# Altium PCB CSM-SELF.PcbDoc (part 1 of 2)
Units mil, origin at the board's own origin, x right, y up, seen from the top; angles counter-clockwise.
Board outline 6400 x 4000 mil, 2 copper layers (Top Layer, Bottom Layer), stack 62 mil thick; 115 components, 107 nets, 450 pads, 129 vias.
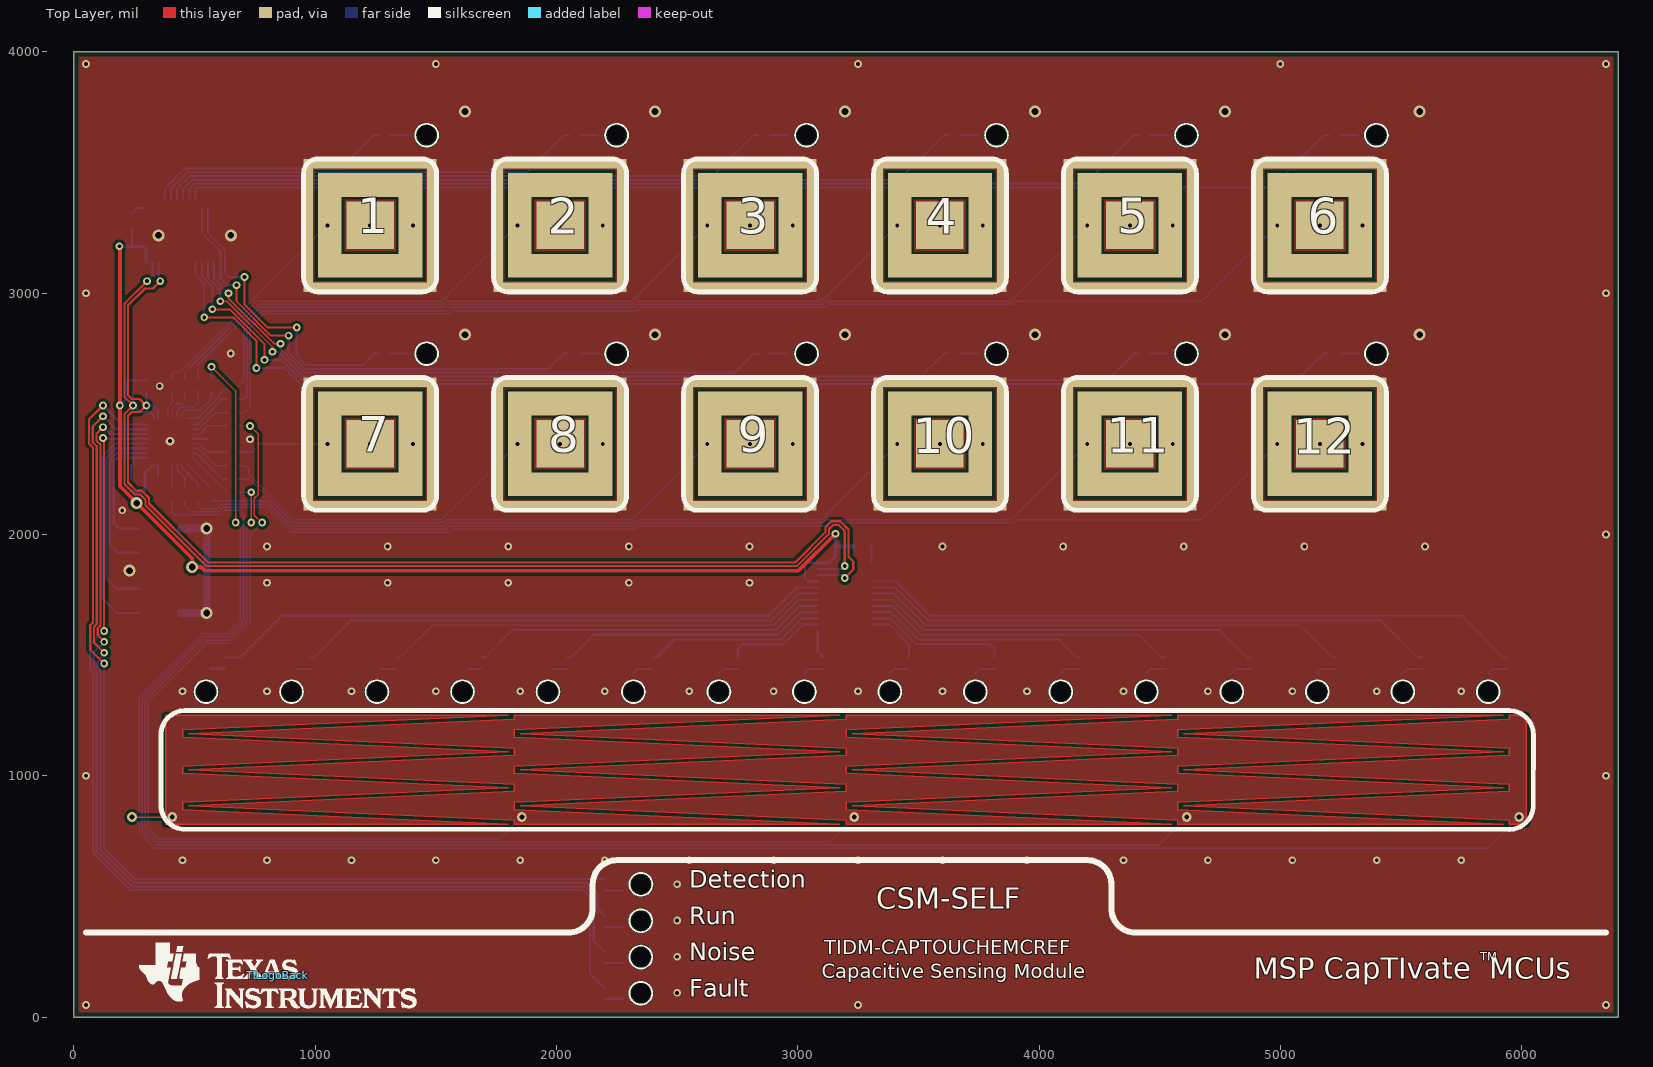
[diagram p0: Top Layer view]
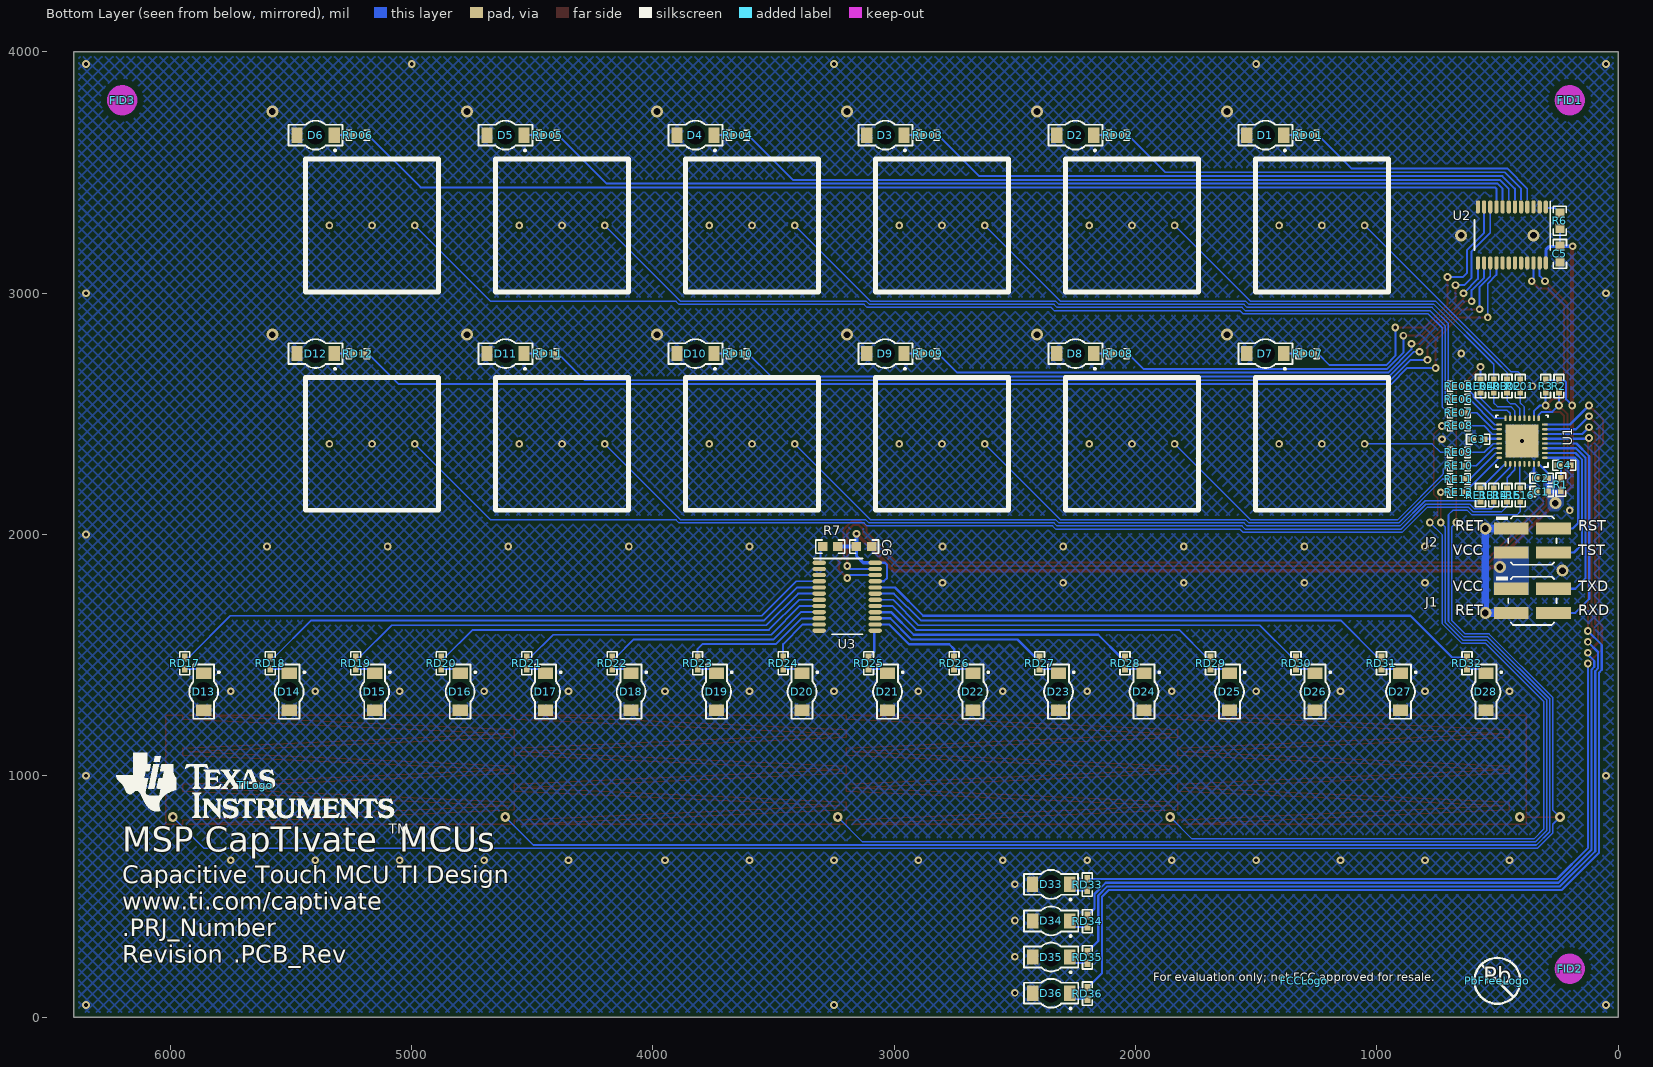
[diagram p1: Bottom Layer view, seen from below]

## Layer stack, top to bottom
Top Solder: solder mask 0.4, Solder Resist, Dk 3.5
Top Layer: signal copper 1.4
Dielectric1: core 59.2, FR-4, Dk 4.8
Bottom Layer: signal copper 1.4
Bottom Solder: solder mask 0.4, Solder Resist, Dk 3.5

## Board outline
0,0 6400,0 6400,4000 0,4000

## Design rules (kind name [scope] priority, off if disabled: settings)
AcuteAngle [All] p1: minimum=4.50000000000000E+0001 checktracksonly=FALSE
AssemblyTestPointUsage [All] p1: valid=2
Clearance Clearance_Keepouts [((IsTrack Or IsArc) And Not InPoly) And IsFree and IsKeepOut vs ((IsTrack Or IsArc) And Not InPoly) And IsFree and IsKeepOut] p1: gap=0
Clearance Clearance_BoardEdge_MountingHoles [OnCopper and InComponentClass('Mounting Holes') vs IsKeepOut] p2: gap=40
Clearance Clearance_BoardEdge_Poly [OnCopper and InPoly vs IsKeepOut] p3: gap=25
Clearance Clearance_BoardEdge [OnCopper and Not InComponentClass('Logo') and not InComponentClass('FiducialMark') and not InRegion(1000,500,4000,800) and Not IsKeepout vs IsKeepOut] p4: gap=75
Clearance Clearance_Poly [InPolygon] p5: gap=12
Clearance [All] p6: gap=6.3
ComponentClearance ComponentClearance_MountingHoles_FiducialMarks [InComponentClass('Mounting Holes') vs InComponentClass('FiducialMark')] p1: gap=50 collisioncheckmode=3 verticalgap=10 showdistances=FALSE
ComponentClearance ComponentClearance_Shunt [InComponentClass('Header') vs InComponentClass('Shunt')] p2: gap=0 collisioncheckmode=3 verticalgap=0 showdistances=FALSE
ComponentClearance ComponentClearance_Logo [InComponentClass('Logo')] p3: gap=50 collisioncheckmode=3 verticalgap=10 showdistances=FALSE
ComponentClearance ComponentClearance_ScrewToNut [(HasFootprint('NY PMS 440 0025 PH')) vs (HasFootprint('Keystone_1902C'))] p4: gap=5 collisioncheckmode=3 verticalgap=10 showdistances=FALSE
ComponentClearance ComponentClearance_MountingHoles [InComponentClass('Mounting Holes')] p5: gap=250 collisioncheckmode=3 verticalgap=100000 showdistances=FALSE
ComponentClearance ComponentClearance_SmallPassives [HasFootprint('0201*') or HasFootprint('0402*') or HasFootprint('0508') or HasFootprint('0603*') or HasFootprint('0612') or HasFootprint('0805*') or HasFootprint('0815*') or HasFootprint('0830*') or HasFootprint('1206*') or HasFootprint('1210*') or HasFootprint('1808*') or HasFootprint('1812*') or HasFootprint('1825*') or HasFootprint('2010*') or HasFootprint('2220*') or HasFootprint('2225*') or HasFootprint('2512*') or HasFootprint('2728*') or HasFootprint('3518*') vs HasFootprint('0201*') or HasFootprint('0402*') or HasFootprint('0508') or HasFootprint('0603*') or HasFootprint('0612') or HasFootprint('0805*') or HasFootprint('0815*') or HasFootprint('0830*') or HasFootprint('1206*') or HasFootprint('1210*') or HasFootprint('1808*') or HasFootprint('1812*') or HasFootprint('1825*') or HasFootprint('2010*') or HasFootprint('2220*') or HasFootprint('2225*') or HasFootprint('2512*') or HasFootprint('2728*') or HasFootprint('3518*')] p6: gap=7.87 collisioncheckmode=3 verticalgap=10 showdistances=FALSE
ComponentClearance ComponentClearance_THtoSMT [IsThruComponent vs IsSMTComponent] p7: gap=7.87 collisioncheckmode=3 verticalgap=30 showdistances=FALSE
ComponentClearance ComponentClearance_THtoTH [IsThruComponent vs IsThruComponent] p8: gap=7.87 collisioncheckmode=3 verticalgap=30 showdistances=FALSE
ComponentClearance [All] p9: gap=7.87 collisioncheckmode=3 verticalgap=10 showdistances=FALSE
DiffPairsRouting [All] p1: maxlimit=100 minlimit=10 mostfreqgap=10 toplayer_minwidth=15 toplayer_maxwidth=15 toplayer_prefwidth=15 bottomlayer_minwidth=15 bottomlayer_maxwidth=15 bottomlayer_prefwidth=15 maxuncoupledlength=1000
FabricationTestPointUsage TestPointUsage [All] p1: valid=2 allowmultiple=FALSE
FabricationTestpoint Testpoint [All] p1: side=3 testpointundercomponent=TRUE minsize=40 maxsize=100 preferedsize=60 minholesize=0 maxholesize=40 preferedholesize=32 testpointgrid=1 allowsidetop=TRUE allowsidebottom=TRUE usegrid=TRUE gridtolerance=0.01
FanoutControl Fanout_LCC [IsLCC] p1: bgadir=Out bgaviamode=Centered fanoutstyle=Auto fanoutdirection=Alternating viagrid=1 // Fanout_LCC (Default Rule)
FanoutControl Fanout_BGA [IsBGA] p2: bgadir=Out bgaviamode=Centered fanoutstyle=Auto fanoutdirection=Alternating viagrid=1 // Fanout_BGA (Default Rule)
FanoutControl Fanout_Default [All] p4: bgadir=Out bgaviamode=Centered fanoutstyle=Auto fanoutdirection=Alternating viagrid=1 // Fanout_Default (Default Rule)
FanoutControl Fanout_Small [(CompPinCount < 5)] p5: bgadir=Out bgaviamode=Centered fanoutstyle=Auto fanoutdirection=OutThenIn viagrid=1 // Fanout_Small (Default Rule)
HoleSize [All] p1: absolutevalues=TRUE maxlimit=251 minlimit=8 maxpercent=80.000 minpercent=20.000
MinimumAnnularRing MinimumAnnularRing_ThermalPadVias [IsVia and InAnyComponent] p1: minimumring=5.91
MinimumAnnularRing [All] p2: minimumring=3.94
MinimumSolderMaskSliver MinimumSolderMaskSliver_Logo [InComponentClass('Logo') vs InComponentClass('Logo')] p1: minsoldermaskwidth=0.7
MinimumSolderMaskSliver [All] p2: minsoldermaskwidth=3.94
PlaneClearance [All] p1: clearance=19.68
PlaneConnect [All] p1: planeconnectstyle=Relief reliefexpansion=10 reliefentries=4 reliefconductorwidth=10 reliefairgap=10
PolygonConnect [All] p1: connectstyle=Direct reliefconductorwidth=10 reliefentries=4 polygonreliefangle="90 Angle" airgapwidth=10
RoutingVias ThermalPadVias [IsVia and InAnyComponent] p1: holewidth=7.87 width=19.68 viastyle="Through Hole" minholewidth=7.87 minwidth=19.68 maxholewidth=12.99 maxwidth=23.62
RoutingVias [All] p2: holewidth=16 width=34 viastyle="Through Hole" minholewidth=7.87 minwidth=26 maxholewidth=40 maxwidth=65
SilkToBoardRegionClearance [Not ((IsComment or IsDesignator) And (Hide <> 'False')) and not InRegion(1000,500,4000,800)] p1:
SilkToSilkClearance SilkToSilkClearance_Pb-FreeLogo [(HasFootprint('Pb-Free_Overlay_Medium') OR HasFootprint('Pb-Free_Overlay_Small')) vs (HasFootprint('Pb-Free_Overlay_Medium') OR HasFootprint('Pb-Free_Overlay_Small'))] p1: silktosilkclearance=0
SilkToSilkClearance [All] p2: silktosilkclearance=5
SilkToSolderMaskClearance "Silk to Solder Mask Opening" [All] p1: minsilkscreentomaskgap=1 clearancetoexposedcopper=FALSE
SolderMaskExpansion [All] p1: expansion=1.9
Width [All] p1: maxlimit=100 minlimit=6 preferedwidth=10 checkconnectedcopper=TRUE
14 further rules are at their usual default settings.

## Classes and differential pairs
component class FiducialMark: FID1 FID2 FID3
component class Logo: TILogo TILogoBack
component class CSM-SELF__TopLevel: FCCLogo FID1 FID2 FID3 PbFreeLogo TILogo TILogoBack
component class CSM-SELF__LEDDrive: C5 C6 D1 D2 D3 D4 D5 D6 D7 D8 D9 D10 D11 D12 D13 D14 D15 D16 D17 D18 D19 D20 D21 D22 D23 D24 D25 D26 D27 D28 D33 D34 D35 D36 R6 R7 RD01 RD02 RD03 RD04 RD05 RD06 RD07 RD08 RD09 RD10 RD11 RD12 RD17 RD18 RD19 RD20 RD21 RD22 RD23 RD24 RD25 RD26 RD27 RD28 RD29 RD30 RD31 RD32 RD33 RD34 RD35 RD36 U2 U3
component class Header: J1 J2
component class CSM-SELF__MCU: C1 C2 C3 C4 J1 J2 R1 R2 R3 U1
net class LED[1..28]: LED1 LED2 LED3 LED4 LED5 LED6 LED7 LED8 LED9 LED10 LED11 LED12 LED13 LED14 LED15 LED16 LED17 LED18 LED19 LED20 LED21 LED22 LED23 LED24 LED25 LED26 LED27 LED28
component class CSM-SELF__CapacitiveTouch: 1 2 3 4 5 6 7 8 9 10 11 12 RE01 RE02 RE03 RE04 RE05 RE06 RE07 RE08 RE09 RE10 RE11 RE12 RE13 RE14 RE15 RE16

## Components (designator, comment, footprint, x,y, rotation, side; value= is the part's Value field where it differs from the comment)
1 "Btn-Self-EMC" btn-self-emc 951.81,3005.51 r0 top
2 "Btn-Self-EMC" btn-self-emc 1739.21,3005.51 r0 top
3 "Btn-Self-EMC" btn-self-emc 2526.61,3005.51 r0 top
4 "Btn-Self-EMC" btn-self-emc 3314.02,3005.51 r0 top
5 "Btn-Self-EMC" btn-self-emc 4101.42,3005.51 r0 top
6 "Btn-Self-EMC" btn-self-emc 4888.82,3005.51 r0 top
7 "Btn-Self-EMC" btn-self-emc 951.81,2100 r0 top
8 "Btn-Self-EMC" btn-self-emc 1739.21,2100 r0 top
9 "Btn-Self-EMC" btn-self-emc 2526.61,2100 r0 top
10 "Btn-Self-EMC" btn-self-emc 3314.02,2100 r0 top
11 "Btn-Self-EMC" btn-self-emc 4101.42,2100 r0 top
12 "Btn-Self-EMC" btn-self-emc 4888.82,2100 r0 top
C1 "C1005X5R0J475M050BC" 0402 316.83,2178.05 r0 bottom
C2 "C1005X5R0J104K" 0402 316.83,2233.05 r0 bottom
C3 "C1005X5R0J105M" 0402 580,2395 r0 bottom
C4 "GRM1555C1E511JA01D" 0402 222.9,2286.98 r180 bottom
C5 "0603YC104JAT2A" 0603 241.18,3162.99 r270 bottom
C6 "0603YC104JAT2A" 0603 3125,1949.61 r180 bottom
D1 "Orange LED" 1206_ReverseMount_LED 1361.26,3623.62 r0 top
D2 "Orange LED" 1206_ReverseMount_LED 2148.66,3623.62 r0 top
D3 "Orange LED" 1206_ReverseMount_LED 2936.06,3623.62 r0 top
D4 "Orange LED" 1206_ReverseMount_LED 3723.46,3623.62 r0 top
D5 "Orange LED" 1206_ReverseMount_LED 4510.87,3623.62 r0 top
D6 "Orange LED" 1206_ReverseMount_LED 5298.27,3623.62 r0 top
D7 "Orange LED" 1206_ReverseMount_LED 1361.26,2718.11 r0 top
D8 "Orange LED" 1206_ReverseMount_LED 2148.66,2718.11 r0 top
D9 "Orange LED" 1206_ReverseMount_LED 2936.06,2718.11 r0 top
D10 "Orange LED" 1206_ReverseMount_LED 3723.46,2718.11 r0 top
D11 "Orange LED" 1206_ReverseMount_LED 4510.87,2718.11 r0 top
D12 "Orange LED" 1206_ReverseMount_LED 5298.27,2718.11 r0 top
D13 "Orange LED" 1206_ReverseMount_LED 5830.79,1448.82 r270 top
D14 "Orange LED" 1206_ReverseMount_LED 5476.46,1448.82 r270 top
D15 "Orange LED" 1206_ReverseMount_LED 5122.13,1448.82 r270 top
D16 "Orange LED" 1206_ReverseMount_LED 4767.8,1448.82 r270 top
D17 "Orange LED" 1206_ReverseMount_LED 4413.46,1448.82 r270 top
D18 "Orange LED" 1206_ReverseMount_LED 4059.13,1448.82 r270 top
D19 "Orange LED" 1206_ReverseMount_LED 3704.8,1448.82 r270 top
D20 "Orange LED" 1206_ReverseMount_LED 3350.47,1448.82 r270 top
D21 "Orange LED" 1206_ReverseMount_LED 2996.14,1448.82 r270 top
D22 "Orange LED" 1206_ReverseMount_LED 2641.81,1448.82 r270 top
D23 "Orange LED" 1206_ReverseMount_LED 2287.48,1448.82 r270 top
D24 "Orange LED" 1206_ReverseMount_LED 1933.15,1448.82 r270 top
D25 "Orange LED" 1206_ReverseMount_LED 1578.82,1448.82 r270 top
D26 "Orange LED" 1206_ReverseMount_LED 1224.49,1448.82 r270 top
D27 "Orange LED" 1206_ReverseMount_LED 870.16,1448.82 r270 top
D28 "Orange LED" 1206_ReverseMount_LED 515.83,1448.82 r270 top
D33 "Yellow-Green LED" 1206_ReverseMount_LED 2249.61,518.5 r0 top
D34 "Yellow-Green LED" 1206_ReverseMount_LED 2249.21,367.01 r0 top
D35 "Yellow LED" 1206_ReverseMount_LED 2249.21,217.01 r0 top
D36 "Red LED" 1206_ReverseMount_LED 2249.21,67.01 r0 top
FCCLogo "FCC disclaimer" FCC_disclaimer 1300,150 r180 bottom
FID1 "Fiducial" Fiducial10-30 200,3800 r180 bottom
FID2 "Fiducial" Fiducial10-30 200,200 r180 bottom
FID3 "Fiducial" Fiducial10-30 6200,3800 r180 bottom
J1 "15-91-2040" Molex_15-91-2040 355,1725.01 r270 bottom
J2 "15-91-2040" Molex_15-91-2040 355,1975 r270 bottom
PbFreeLogo "Pb-Free Symbol" Pb-Free_Overlay_Medium 500,150 r180 bottom
R1 "CRCW040247K0JNED" 0402 236.83,2206.67 r270 bottom
R2 "CRCW04022K20JNED" 0402 245,2615 r270 bottom
R3 "CRCW04022K20JNED" 0402 300,2615 r270 bottom
R6 "CRCW060310K0JNEA" 0603 241.18,3300.79 r90 bottom
R7 "CRCW060310K0JNEA" 0603 3265,1949.61 r0 bottom
RD01 "CRCW0402620RJNED" 0402 1286.46,3655.12 r0 bottom
RD02 "CRCW0402620RJNED" 0402 2073.86,3655.12 r0 bottom
RD03 "CRCW0402620RJNED" 0402 2861.26,3655.12 r0 bottom
RD04 "CRCW0402620RJNED" 0402 3648.66,3655.12 r0 bottom
RD05 "CRCW0402620RJNED" 0402 4436.06,3655.12 r0 bottom
RD06 "CRCW0402620RJNED" 0402 5223.46,3655.12 r0 bottom
RD07 "CRCW0402620RJNED" 0402 1286.46,2749.61 r0 bottom
RD08 "CRCW0402620RJNED" 0402 2073.86,2749.61 r0 bottom
RD09 "CRCW0402620RJNED" 0402 2861.26,2749.61 r0 bottom
RD10 "CRCW0402620RJNED" 0402 3648.66,2749.61 r0 bottom
RD11 "CRCW0402620RJNED" 0402 4436.06,2749.61 r0 bottom
RD12 "CRCW0402620RJNED" 0402 5223.46,2749.61 r0 bottom
RD17 "CRCW0402620RJNED" 0402 5941.02,1466.54 r270 bottom
RD18 "CRCW0402620RJNED" 0402 5586.69,1466.54 r270 bottom
RD19 "CRCW0402620RJNED" 0402 5232.36,1466.54 r270 bottom
RD20 "CRCW0402620RJNED" 0402 4878.03,1466.54 r270 bottom
RD21 "CRCW0402620RJNED" 0402 4523.7,1466.54 r270 bottom
RD22 "CRCW0402620RJNED" 0402 4169.37,1466.54 r270 bottom
RD23 "CRCW0402620RJNED" 0402 3815.04,1466.54 r270 bottom
RD24 "CRCW0402620RJNED" 0402 3460.71,1466.54 r270 bottom
RD25 "CRCW0402620RJNED" 0402 3106.38,1466.54 r270 bottom
RD26 "CRCW0402620RJNED" 0402 2752.05,1466.54 r270 bottom
RD27 "CRCW0402620RJNED" 0402 2397.72,1466.54 r270 bottom
RD28 "CRCW0402620RJNED" 0402 2043.39,1466.54 r270 bottom
RD29 "CRCW0402620RJNED" 0402 1689.06,1466.54 r270 bottom
RD30 "CRCW0402620RJNED" 0402 1334.72,1466.54 r270 bottom
RD31 "CRCW0402620RJNED" 0402 980.39,1466.54 r270 bottom
RD32 "CRCW0402620RJNED" 0402 626.06,1466.54 r270 bottom
RD33 "CRCW0402620RJNED" 0402 2199.61,548.5 r270 bottom
RD34 "CRCW0402620RJNED" 0402 2199.21,397.01 r270 bottom
RD35 "CRCW0402620RJNED" 0402 2199.21,247.01 r270 bottom
RD36 "CRCW0402620RJNED" 0402 2199.21,97.01 r270 bottom
RE01 "CRCW0402470RJNED" 0402 405,2615 r90 bottom
RE02 "CRCW0402470RJNED" 0402 460,2615 r90 bottom
RE03 "CRCW0402470RJNED" 0402 515,2615 r90 bottom
RE04 "CRCW0402470RJNED" 0402 570,2615 r90 bottom
RE05 "CRCW0402470RJNED" 0402 660,2615 r0 bottom
RE06 "CRCW0402470RJNED" 0402 660,2560 r0 bottom
RE07 "CRCW0402470RJNED" 0402 660,2505 r0 bottom
RE08 "CRCW0402470RJNED" 0402 660,2450 r0 bottom
RE09 "CRCW0402470RJNED" 0402 660,2340 r0 bottom
RE10 "CRCW0402470RJNED" 0402 660,2285 r0 bottom
RE11 "CRCW0402470RJNED" 0402 660,2230 r0 bottom
RE12 "CRCW0402470RJNED" 0402 660,2175 r0 bottom
RE13 "CRCW0402470RJNED" 0402 570,2163.62 r270 bottom
RE14 "CRCW0402470RJNED" 0402 515,2163.62 r270 bottom
RE15 "CRCW0402470RJNED" 0402 460,2163.62 r270 bottom
RE16 "CRCW0402470RJNED" 0402 405,2163.62 r270 bottom
TILogo "Texas Instruments" TI_Stacked_Overlay_Medium 5648.66,960 r180 bottom
TILogoBack "Texas Instruments" TI_Stacked_Overlay_Medium 845,172.71 r0 top
U1 "MSP430FR2633IRHB" RHB0032E_NV 397.9,2386.98 r0 bottom
U2 "TCA9535PWR" PW0024A_N 440,3241.73 r270 bottom
U3 "TCA9535PWR" PW0024A_N 3194.96,1742.13 r180 bottom

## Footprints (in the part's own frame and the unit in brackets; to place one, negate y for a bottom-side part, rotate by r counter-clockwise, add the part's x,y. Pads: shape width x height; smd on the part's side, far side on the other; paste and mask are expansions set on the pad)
0402 [mm] "0402 from SM-752 data"
  rect 0.8x0.6 smd: 1(-0.6,0) 2(0.6,0)
  silkscreen extent -1.22,-0.52 1.22,0.52, body extent -0.55,-0.3 0.55,0.3, height 0.6
0603 [mm] "0603 from SM-752 data"
  rect 1x0.95 smd: 1(-0.8,0) 2(0.8,0)
  silkscreen extent -1.52,-0.69 1.52,0.69, body extent -0.87,-0.47 0.87,0.47, height 1
1206_ReverseMount_LED [mm]
  rect 1.2x1.6 smd far side: 1(0.6,0.8) 2(4.5,0.8)
  round 0 hole 2 unplated: ""(2.55,0.8)
  silkscreen extent 1.35,-0.4 3.75,2
btn-self-emc [mm] "Mutual Capacitance Button with EMC"
  rect 1x14 smd paste+0: GND(0.5,7)
  rect 14x1 smd paste+0 mask+0: GND(7,0.5) GND(7,13.5)
  round 0.81 hole 0.406: GND(7,7) RX(2.5,7) RX(11.5,7)
  rect 5x5 smd paste+0 mask+0: GND(7,7)
  rect 1x14 smd paste+0 mask+0: GND(13.5,7)
  rect 2.5x11 smd paste+0: RX(2.75,7) RX(11.25,7)
  rect 11x2.5 smd paste+0: RX(7,2.75) RX(7,11.25)
  silkscreen extent 0,0 14,14
FCC_disclaimer [mil]
Fiducial10-30 [mm]
  round 1 smd mask+1: 1(0,0)
  Top Layer keep-out circle w1.678: c0,0 r0.75
Molex_15-91-2040 [mil] "Molex"
  rect 50x144.88 smd: 1(-50,-87.5) 2(-50,87.5) 3(50,-87.5) 4(50,87.5)
  silkscreen extent -100,-150 100,100, body extent -100,-137 100,138, height 380
Pb-Free_Overlay_Medium [mil]
  silkscreen extent -95,-95 95,95
PW0024A_N [mm] "TSOP, 24-Leads, Body 7.8x4.4mm, Pitch 0.65mm, IPC Medium Density"
  oval 1.4x0.45 smd: 1(-2.95,3.575) 2(-2.95,2.925) 3(-2.95,2.275) 4(-2.95,1.625) 5(-2.95,0.975) 6(-2.95,0.325) 7(-2.95,-0.325) 8(-2.95,-0.975) 9(-2.95,-1.625) 10(-2.95,-2.275) 11(-2.95,-2.925) 12(-2.95,-3.575) 13(2.95,-3.575) 14(2.95,-2.925) 15(2.95,-2.275) 16(2.95,-1.625) 17(2.95,-0.975) 18(2.95,-0.325) 19(2.95,0.325) 20(2.95,0.975) 21(2.95,1.625) 22(2.95,2.275) 23(2.95,2.925) 24(2.95,3.575)
  silkscreen extent -3.51,-3.95 1.6,4.04, body extent -3.21,-3.9 3.21,3.9, height 1
RHB0032E_NV [mm] "QFN, 32-Leads, Body 5x5mm, Pitch 0.5mm, Thermal Pad 3.45x3.45mm, TI Recommended"
  oval 0.6x0.24 smd: 1(-2.4,1.75) 2(-2.4,1.25) 3(-2.4,0.75) 4(-2.4,0.25) 5(-2.4,-0.25) 6(-2.4,-0.75) 7(-2.4,-1.25) 8(-2.4,-1.75) 17(2.4,-1.75) 18(2.4,-1.25) 19(2.4,-0.75) 20(2.4,-0.25) 21(2.4,0.25) 22(2.4,0.75) 23(2.4,1.25) 24(2.4,1.75)
  oval 0.24x0.6 smd: 9(-1.75,-2.4) 10(-1.25,-2.4) 11(-0.75,-2.4) 12(-0.25,-2.4) 13(0.25,-2.4) 14(0.75,-2.4) 15(1.25,-2.4) 16(1.75,-2.4) 25(1.75,2.4) 26(1.25,2.4) 27(0.75,2.4) 28(0.25,2.4) 29(-0.25,2.4) 30(-0.75,2.4) 31(-1.25,2.4) 32(-1.75,2.4)
  rect 3.45x3.45 smd paste-1.725: 33(0,0)
  silkscreen extent -2.72,-2.73 2.72,2.73, body extent -2.57,-2.57 2.58,2.58, height 1.01
TI_Stacked_Overlay_Medium [mil]
  silkscreen extent -576,-136 576,135

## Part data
1 2 3 4 5 6 7 8 9 10 11 12: library part btn-self-emc, "Capacitive Button, Self Capacitance, 2-Layer, High EMC"
C1: "CAP, CERM, 4.7 µF, 6.3 V, +/- 20%, X5R, 0402"
C2: "CAP, CERM, 0.1 µF, 6.3 V, +/- 10%, X5R, 0402"
C3: "CAP, CERM, 1 µF, 6.3 V, +/- 20%, X5R, 0402"
C4: "CAP, CERM, 510 pF, 25 V, +/- 5%, C0G/NP0, 0402"
C5 C6: "CAP, CERM, 0.1 µF, 16 V, +/- 5%, X7R, 0603"
D1 D2 D3 D4 D5 D6 D7 D8 D9 D10 D11 D12 D13 D14 D15 D16 D17 D18 D19 D20 D21 D22 D23 D24 D25 D26 D27 D28: library part 597-6201-607F, "LED, Orange, SMD, Reverse Mount, 1206"
D33 D34: library part 597-6501-607F, "LED, Yellow-Green, SMD, Reverse Mount, 1206"
D35: library part 597-6401-607F, "LED, Yellow, SMD, Reverse Mount, 1206"
D36: library part 597-6001-607F, "LED, Red, SMD, Reverse Mount, 1206"
FCCLogo: library part FCC_disclaimer, "FCC_disclaimer"
FID1 FID2 FID3: "Fiducial mark.  There is nothing to buy or mount."
J1 J2: "Header, 100mil, 2x2, Tin, SMT"
PbFreeLogo: library part Pb-Free
R1: "RES, 47 k, 5%, 0.063 W, 0402"
R2 R3: "RES, 2.2 k, 5%, 0.063 W, 0402"
R6 R7: "RES, 10 k, 5%, 0.1 W, 0603"
RD01 RD02 RD03 RD04 RD05 RD06 RD07 RD08 RD09 RD10 RD11 RD12 RD17 RD18 RD19 RD20 RD21 RD22 RD23 RD24 RD25 RD26 RD27 RD28 RD29 RD30 RD31 RD32 RD33 RD34 RD35 RD36: "RES, 620, 5%, 0.063 W, 0402"
RE01 RE02 RE03 RE04 RE05 RE06 RE07 RE08 RE09 RE10 RE11 RE12 RE13 RE14 RE15 RE16: "RES, 470, 5%, 0.063 W, 0402"
TILogo TILogoBack: library part TI_Logo, "Texas Instrument Corporate Signature"
U1: "MSP430 Captivate Microcontroller"
U2 U3: "Remote 16-Bit I2C and SMBus, Low-Power I/O Expander with Interrupt Output and Config Register, 1.65 to 5.5 V, -40 to 85 degC, 24-pin TSSOP (PW), Green (RoHS & no Sb/Br)"

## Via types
v1: diameter 32, hole 16, Top Layer to Bottom Layer, tented both sides, 103 vias
v2: diameter 50, hole 28, Top Layer to Bottom Layer, tented both sides, 19 vias
v3: diameter 40, hole 20, Top Layer to Bottom Layer, tented both sides, 6 vias
v4: diameter 36, hole 16, Top Layer to Bottom Layer, 1 vias

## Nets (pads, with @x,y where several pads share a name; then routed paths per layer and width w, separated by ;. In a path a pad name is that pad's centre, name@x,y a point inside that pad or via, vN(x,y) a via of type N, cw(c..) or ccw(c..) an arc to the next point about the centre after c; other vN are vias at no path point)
CAP0.0: RE01.1 U1.12 | length 116.9
  Bottom Layer w6.3: U1.12@388.05,2481.47 388.05,2528.05 405,2545 RE01.1@405,2591.38
CAP0.1: RE02.1 U1.13 | length 143.3
  Bottom Layer w6.3: U1.13@407.74,2481.47 407.74,2522.74 427.6,2542.6 447.6,2542.6 460,2555 RE02.1@460,2591.38
CAP0.2: RE03.1 U1.14 | length 184.5
  Bottom Layer w6.3: U1.14@427.42,2481.47 427.42,2512.42 445,2530 500,2530 515,2545 RE03.1@515,2591.38 ; RE03.1@510.69,2595.69 RE03.1@515,2600
CAP0.3: RE04.1 U1.15 | length 196
  Bottom Layer w6.3: U1.15@447.11,2481.47 447.11,2502.11 460,2515 520,2515 570,2565 RE04.1@570,2591.38
CAP1.0: RE05.1 U1.16 | length 215.2
  Bottom Layer w6: U1.16@466.8,2481.47 511.47,2481.47 600,2570 600,2580 RE05.1@625,2605
CAP1.1: RE06.1 U1.17 | length 187.1
  Bottom Layer w6: U1.17@492.39,2455.88 510.88,2455.88 615,2560 RE06.1@636.38,2560
CAP1.2: RE07.1 U1.18 | length 172.5
  Bottom Layer w6: U1.18@492.39,2436.2 516.2,2436.2 585,2505 RE07.1@636.38,2505
CAP1.3: RE08.1 U1.19 | length 157.9
  Bottom Layer w6: U1.19@492.39,2416.51 521.51,2416.51 555,2450 RE08.1@636.38,2450
CAP2.0: RE09.1 U1.21 | length 159.4
  Bottom Layer w6: U1.21@492.39,2377.14 517.86,2377.14 555,2340 RE09.1@636.38,2340
CAP2.1: RE10.1 U1.22 | length 174
  Bottom Layer w6: U1.22@492.39,2357.46 514.74,2357.46 587.2,2285 RE10.1@636.38,2285
CAP2.2: RE11.1 U1.23 | length 188.6
  Bottom Layer w6: U1.23@492.39,2337.77 507.23,2337.77 615,2230 RE11.1@636.38,2230
CAP2.3: RE12.1 U1.24 | length 194.6
  Bottom Layer w6: U1.24@492.39,2318.09 RE12.1@630,2180.47
CAP3.0: RE13.1 U1.25 | length 146
  Bottom Layer w6: U1.25@466.8,2292.5 RE13.1@570,2189.29
CAP3.1: RE14.1 U1.26 | length 133.4
  Bottom Layer w6: U1.26@447.11,2292.5 447.11,2277.89 515,2210 RE14.1@515,2187.24
CAP3.2: RE15.1 U1.27 | length 118.7
  Bottom Layer w6: U1.27@427.42,2292.5 427.42,2267.58 460,2235 RE15.1@460,2187.24
CAP3.3: RE16.1 U1.28 | length 102.5
  Bottom Layer w6.3: RE16.1@407.74,2189.98 U1.28@407.74,2292.5
CAPTIVATE_VREG: C3.1 U1.20 | length 62.2
  Bottom Layer w9: U1.20@492.39,2396.83 C3.1@554.55,2396.83
DETECT: RD33.1 U1.8 | length 4237.9
  Top Layer w9: v1(120,2535) 62.6,2477.6 62.6,2376.23 79.1,2359.73 79.1,1635.27 67.6,1623.77 67.6,1522.4 v1(125,1465)
  Bottom Layer w9: v1(120,2535) 199.12,2455.88 U1.8@303.41,2455.88 ; v1(125,1465) 125,700 252.87,572.13 RD33.1@2199.61,572.13
FAULT: RD36.1 U1.5 | length 4457
  Top Layer w9: v1(125,1600) v1@125,2395
  Bottom Layer w9: v1(125,1600) 67.6,1542.6 67.6,1438.83 79.1,1427.33 79.1,680.99 233.86,526.23 2110.5,526.23 2139.4,497.33 2139.4,180.44 RD36.1@2199.21,120.63 ; v1@126.83,2396.83 U1.5@303.41,2396.83
  other v1: 120,2400
LED1: D1.1 RD01.2 | length 74.8
  Bottom Layer w7.87: RD01.2@1310.08,3655.12 D1.1@1384.88,3655.12
LED2: D2.1 RD02.2 | length 74.8
  Bottom Layer w7.87: RD02.2@2097.48,3655.12 D2.1@2172.28,3655.12
LED3: D3.1 RD03.2 | length 74.8
  Bottom Layer w7.87: RD03.2@2884.88,3655.12 D3.1@2959.68,3655.12
LED4: D4.1 RD04.2 | length 74.8
  Bottom Layer w7.87: RD04.2@3672.28,3655.12 D4.1@3747.09,3655.12
LED5: D5.1 RD05.2 | length 74.8
  Bottom Layer w7.87: RD05.2@4459.69,3655.12 D5.1@4534.49,3655.12
LED6: D6.1 RD06.2 | length 74.8
  Bottom Layer w7.87: RD06.2@5247.09,3655.12 D6.1@5321.89,3655.12
LED7: D7.1 RD07.2 | length 74.8
  Bottom Layer w7.87: RD07.2@1310.08,2749.61 D7.1@1384.88,2749.61
LED8: D8.1 RD08.2 | length 74.8
  Bottom Layer w7.87: RD08.2@2097.48,2749.61 D8.1@2172.28,2749.61
LED9: D9.1 RD09.2 | length 74.8
  Bottom Layer w7.87: RD09.2@2884.88,2749.61 D9.1@2959.68,2749.61
LED10: D10.1 RD10.2 | length 74.8
  Bottom Layer w7.87: RD10.2@3672.28,2749.61 D10.1@3747.09,2749.61
LED11: D11.1 RD11.2 | length 74.8
  Bottom Layer w7.87: RD11.2@4459.69,2749.61 D11.1@4534.49,2749.61
LED12: D12.1 RD12.2 | length 74.8
  Bottom Layer w7.87: RD12.2@5247.09,2749.61 D12.1@5321.89,2749.61
LED13: D13.1 RD17.2 | length 86.1
  Bottom Layer w7.87: D13.1@5862.28,1425.2 5880,1442.91 RD17.2@5941.02,1442.91
LED14: D14.1 RD18.2 | length 86.1
  Bottom Layer w7.87: D14.1@5507.95,1425.2 5525.67,1442.91 RD18.2@5586.69,1442.91
LED15: D15.1 RD19.2 | length 86.1
  Bottom Layer w7.87: D15.1@5153.62,1425.2 5171.34,1442.91 RD19.2@5232.36,1442.91
LED16: D16.1 RD20.2 | length 86.1
  Bottom Layer w7.87: D16.1@4799.29,1425.2 4817.01,1442.91 RD20.2@4878.03,1442.91
LED17: D17.1 RD21.2 | length 86.1
  Bottom Layer w7.87: D17.1@4444.96,1425.2 4462.68,1442.91 RD21.2@4523.7,1442.91
LED18: D18.1 RD22.2 | length 86.1
  Bottom Layer w7.87: D18.1@4090.63,1425.2 4108.35,1442.91 RD22.2@4169.37,1442.91
LED19: D19.1 RD23.2 | length 86.1
  Bottom Layer w7.87: D19.1@3736.3,1425.2 3754.02,1442.91 RD23.2@3815.04,1442.91
LED20: D20.1 RD24.2 | length 86.1
  Bottom Layer w7.87: D20.1@3381.97,1425.2 3399.68,1442.91 RD24.2@3460.71,1442.91
LED21: D21.1 RD25.2 | length 86.1
  Bottom Layer w7.87: D21.1@3027.64,1425.2 3045.35,1442.91 RD25.2@3106.38,1442.91
LED22: D22.1 RD26.2 | length 86.1
  Bottom Layer w7.87: D22.1@2673.31,1425.2 2691.02,1442.91 RD26.2@2752.05,1442.91
LED23: D23.1 RD27.2 | length 86.1
  Bottom Layer w7.87: D23.1@2318.98,1425.2 2336.69,1442.91 RD27.2@2397.72,1442.91
LED24: D24.1 RD28.2 | length 61
  Bottom Layer w7.87: D24.1@1982.36,1442.91 RD28.2@2043.39,1442.91
LED25: D25.1 RD29.2 | length 61
  Bottom Layer w7.87: D25.1@1628.03,1442.91 RD29.2@1689.06,1442.91
LED26: D26.1 RD30.2 | length 61
  Bottom Layer w7.87: D26.1@1273.7,1442.91 RD30.2@1334.72,1442.91
LED27: D27.1 RD31.2 | length 61
  Bottom Layer w7.87: D27.1@919.37,1442.91 RD31.2@980.39,1442.91
LED28: D28.1 RD32.2 | length 61
  Bottom Layer w9.84: D28.1@565.04,1442.91 RD32.2@626.06,1442.91
NetD33_1: D33.1 RD33.2 | length 75
  Bottom Layer w9: RD33.2@2199.61,524.88 D33.1@2274.61,524.88
NetD34_1: D34.1 RD34.2 | length 75
  Bottom Layer w9: RD34.2@2199.21,373.39 D34.1@2274.21,373.39
NetD35_1: D35.1 RD35.2 | length 75
  Bottom Layer w9: RD35.2@2199.21,223.39 D35.1@2274.21,223.39
NetD36_1: D36.1 RD36.2 | length 75
  Bottom Layer w9: RD36.2@2199.21,75.35 D36.1@2274.21,75.35
NetR6_2: R6.2 U2.1 | length 67
  Bottom Layer w7.87: R6.2@241.18,3332.28 262.83,3353.94 U2.1@299.25,3353.94
NetR7_2: R7.2 U3.1 | length 61.9
  Bottom Layer w7.87: U3.1@3305.2,1888.84 R7.2@3305.2,1950.79
NetRD01_1: RD01.1 U2.4 | length 1024.8
  Bottom Layer w7.87: 376.02,3387.4 376.02,3433.66 459.69,3517.32 1105.35,3517.32 1243.15,3655.12 RD01.1@1262.83,3655.12
NetRD02_1: RD02.1 U2.5 | length 1786.6
  Bottom Layer w7.87: 401.61,3387.4 401.61,3433.66 469.53,3501.57 1877.01,3501.57 2030.55,3655.12 RD02.1@2050.24,3655.12
NetRD03_1: RD03.1 U2.6 | length 2548.4
  Bottom Layer w7.87: 427.2,3387.4 427.2,3433.66 479.37,3485.83 2648.66,3485.83 2817.95,3655.12 RD03.1@2837.64,3655.12
NetRD04_1: RD04.1 U2.7 | length 3310.2
  Bottom Layer w7.87: 452.8,3387.4 452.8,3433.66 489.21,3470.08 3420.31,3470.08 3605.35,3655.12 RD04.1@3625.04,3655.12
NetRD05_1: RD05.1 U2.8 | length 4072
  Bottom Layer w7.87: 478.39,3387.4 478.39,3433.66 499.06,3454.33 4191.97,3454.33 4392.76,3655.12 RD05.1@4412.44,3655.12
NetRD06_1: RD06.1 U2.9 | length 4833.9
  Bottom Layer w7.87: 503.98,3387.4 503.98,3433.66 508.9,3438.58 4963.62,3438.58 5180.16,3655.12 RD06.1@5199.84,3655.12
NetRD07_1: RD07.1 U2.11 | length 1248.9
  Top Layer w7.87: v1(707.03,3067.03) 707.03,2953.1 802.55,2857.58 v1(923.07,2857.58)
  Bottom Layer w7.87: U2.11@555.16,3353.94 555.16,3250.2 625.35,3180 625.35,3084.65 642.97,3067.03 v1(707.03,3067.03) ; v1(923.07,2857.58) 923.07,2740.77 961.48,2702.36 1195.91,2702.36 1243.15,2749.61 RD07.1@1262.83,2749.61
NetRD08_1: RD08.1 U2.10 | length 2028.6
  Top Layer w7.87: v1(673.63,3033.63) 673.63,2966.46 815.91,2824.18 v1(889.66,2824.18)
  Bottom Layer w7.87: U2.10@529.57,3353.94 529.57,3250.43 607.68,3172.32 607.68,3062.32 636.37,3033.63 v1(673.63,3033.63) ; v1(889.66,2824.18) 889.66,2754.13 957.18,2686.61 1967.56,2686.61 2030.55,2749.61 RD08.1@2050.24,2749.61
NetRD09_1: RD09.1 U2.13 | length 2546
  Top Layer w7.87: v1(640.22,3000.22) 640.22,2979.82 829.27,2790.77 v1(856.26,2790.77)
  Bottom Layer w7.87: U2.13@580.75,3129.53 580.75,3059.69 v1(640.22,3000.22) ; v1(856.26,2790.77) 856.26,2767.5 952.89,2670.87 2739.21,2670.87 2817.95,2749.61 RD09.1@2837.64,2749.61
NetRD10_1: RD10.1 U2.14 | length 3382.2
  Top Layer w7.87: v1(606.81,2966.81) 633.19,2966.81 822.85,2777.15 v1(822.85,2757.36)
  Bottom Layer w7.87: U2.14@555.16,3129.53 555.16,3064.84 606.81,3013.19 v1(606.81,2966.81) ; v1(822.85,2757.36) 846.35,2757.36 948.59,2655.12 3510.87,2655.12 3605.35,2749.61 RD10.1@3625.04,2749.61
NetRD11_1: RD11.1 U2.15 | length 4259.8
  Top Layer w7.87: v1(573.41,2933.41) 646.55,2933.41 789.44,2790.51 v1(789.44,2723.96)
  Bottom Layer w7.87: U2.15@529.57,3129.53 529.57,3070.39 573.41,3026.55 v1(573.41,2933.41) ; v1(789.44,2723.96) 859.71,2723.96 944.3,2639.37 4282.52,2639.37 4392.76,2749.61 RD11.1@4412.44,2749.61
NetRD12_1: RD12.1 U2.16 | length 5137.3
  Top Layer w7.87: v1(540,2900) 659.91,2900 756.04,2803.88 v1(756.04,2690.55)
  Bottom Layer w7.87: U2.16@503.98,3129.53 503.98,3075.94 540,3039.91 v1(540,2900) ; v1(756.04,2690.55) 873.07,2690.55 940,2623.62 5054.17,2623.62 5180.16,2749.61 RD12.1@5199.84,2749.61
NetRD17_1: RD17.1 U3.4 | length 2764.7
  Bottom Layer w7.87: U3.4@3307.17,1806.1 3406.57,1806.1 3549.29,1663.39 5752.05,1663.39 5925.28,1490.16 RD17.1@5941.02,1490.16
NetRD18_1: RD18.1 U3.5 | length 2399.8
  Bottom Layer w7.87: U3.5@3307.17,1780.51 3402.64,1780.51 3539.45,1643.7 5417.4,1643.7 5570.94,1490.16 RD18.1@5586.69,1490.16
NetRD19_1: RD19.1 U3.6 | length 2034.9
  Bottom Layer w7.87: U3.6@3307.17,1754.92 3398.7,1754.92 3529.61,1624.02 5082.76,1624.02 5216.61,1490.16 RD19.1@5232.36,1490.16
NetRD20_1: RD20.1 U3.7 | length 1669.9
  Bottom Layer w7.87: U3.7@3307.17,1729.33 3394.76,1729.33 3519.76,1604.33 4748.11,1604.33 4862.28,1490.16 RD20.1@4878.03,1490.16
NetRD21_1: RD21.1 U3.8 | length 1305
  Bottom Layer w7.87: U3.8@3307.17,1703.74 3390.83,1703.74 3509.92,1584.65 4413.46,1584.65 4507.95,1490.16 RD21.1@4523.7,1490.16
NetRD22_1: RD22.1 U3.9 | length 940.1
  Bottom Layer w7.87: U3.9@3307.17,1678.15 3386.89,1678.15 3500.08,1564.96 4078.82,1564.96 4153.62,1490.16 RD22.1@4169.37,1490.16
NetRD23_1: RD23.1 U3.10 | length 595.9
  Bottom Layer w7.87: U3.10@3307.17,1652.56 3382.95,1652.56 3490.24,1545.28 3795.35,1545.28 3815.04,1525.59 RD23.1@3815.04,1490.16
NetRD24_1: RD24.1 U3.11 | length 242.5
  Bottom Layer w7.87: U3.11@3307.17,1626.97 3379.02,1626.97 3460.71,1545.28 RD24.1@3460.71,1490.16
NetRD25_1: RD25.1 U3.13 | length 121
  Bottom Layer w9.84: U3.13@3082.76,1601.38 3082.76,1513.78 RD25.1@3106.38,1490.16
NetRD26_1: RD26.1 U3.14 | length 408.1
  Bottom Layer w9.84: RD26.1@2752.05,1490.16 2752.05,1525.59 2771.73,1545.28 2939.06,1545.28 3020.75,1626.97 U3.14@3082.76,1626.97
NetRD27_1: RD27.1 U3.15 | length 752.3
  Bottom Layer w9.84: RD27.1@2397.72,1490.16 2414.45,1490.16 2489.25,1564.96 2929.21,1564.96 3016.81,1652.56 U3.15@3082.76,1652.56
NetRD28_1: RD28.1 U3.16 | length 1117.2
  Bottom Layer w9.84: RD28.1@2043.39,1490.16 2060.12,1490.16 2154.61,1584.65 2919.37,1584.65 3012.87,1678.15 U3.16@3082.76,1678.15
NetRD29_1: RD29.1 U3.17 | length 1482.2
  Bottom Layer w7.87: RD29.1@1689.06,1490.16 1704.8,1490.16 1818.98,1604.33 2909.53,1604.33 3008.94,1703.74 U3.17@3082.76,1703.74
NetRD30_1: RD30.1 U3.18 | length 1847.1
  Bottom Layer w7.87: RD30.1@1334.72,1490.16 1350.47,1490.16 1484.33,1624.02 2899.69,1624.02 3005,1729.33 U3.18@3082.76,1729.33
NetRD31_1: RD31.1 U3.19 | length 2212
  Bottom Layer w7.87: RD31.1@980.39,1490.16 996.14,1490.16 1149.68,1643.7 2889.84,1643.7 3001.06,1754.92 U3.19@3082.76,1754.92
